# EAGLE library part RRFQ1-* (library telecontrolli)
FSK Superhet Receiver with Crystal Oscillator Source: http://www.telecontrolli.com/eng/default-wproducts.html ... rrfq1.pdf
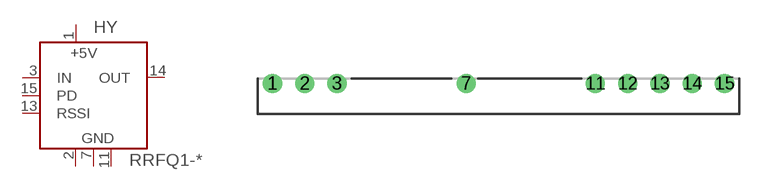
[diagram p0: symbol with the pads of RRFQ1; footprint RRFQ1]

Designator prefix HY

## RRFQ1- (MPN: FM-RRFQ1-868; OC_FARNELL: 1201003; OC_NEWARK: 01M7854)  [RRFQ1]
1  +5V  pwr
2  GND  pwr
3  IN  in
7  GND  pwr
11  GND  pwr
13  RSSI  in
14  OUT  out
15  PD  in

## Footprint RRFQ1 (pad centres in mm)
Ceramic Hybrid Package Source: http://www.telecontrolli.com/eng/default-wproducts.html ... rrfq1.pdf
drill 1 pad 1.422 round: 1 -17.78,0; 2 -15.24,0; 3 -12.7,0; 7 -2.54,0; 11 7.62,0; 12 10.16,0; 13 12.7,0; 14 15.24,0; 15 17.78,0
